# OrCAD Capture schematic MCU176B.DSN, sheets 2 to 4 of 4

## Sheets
2 2_Peripherals: size A3
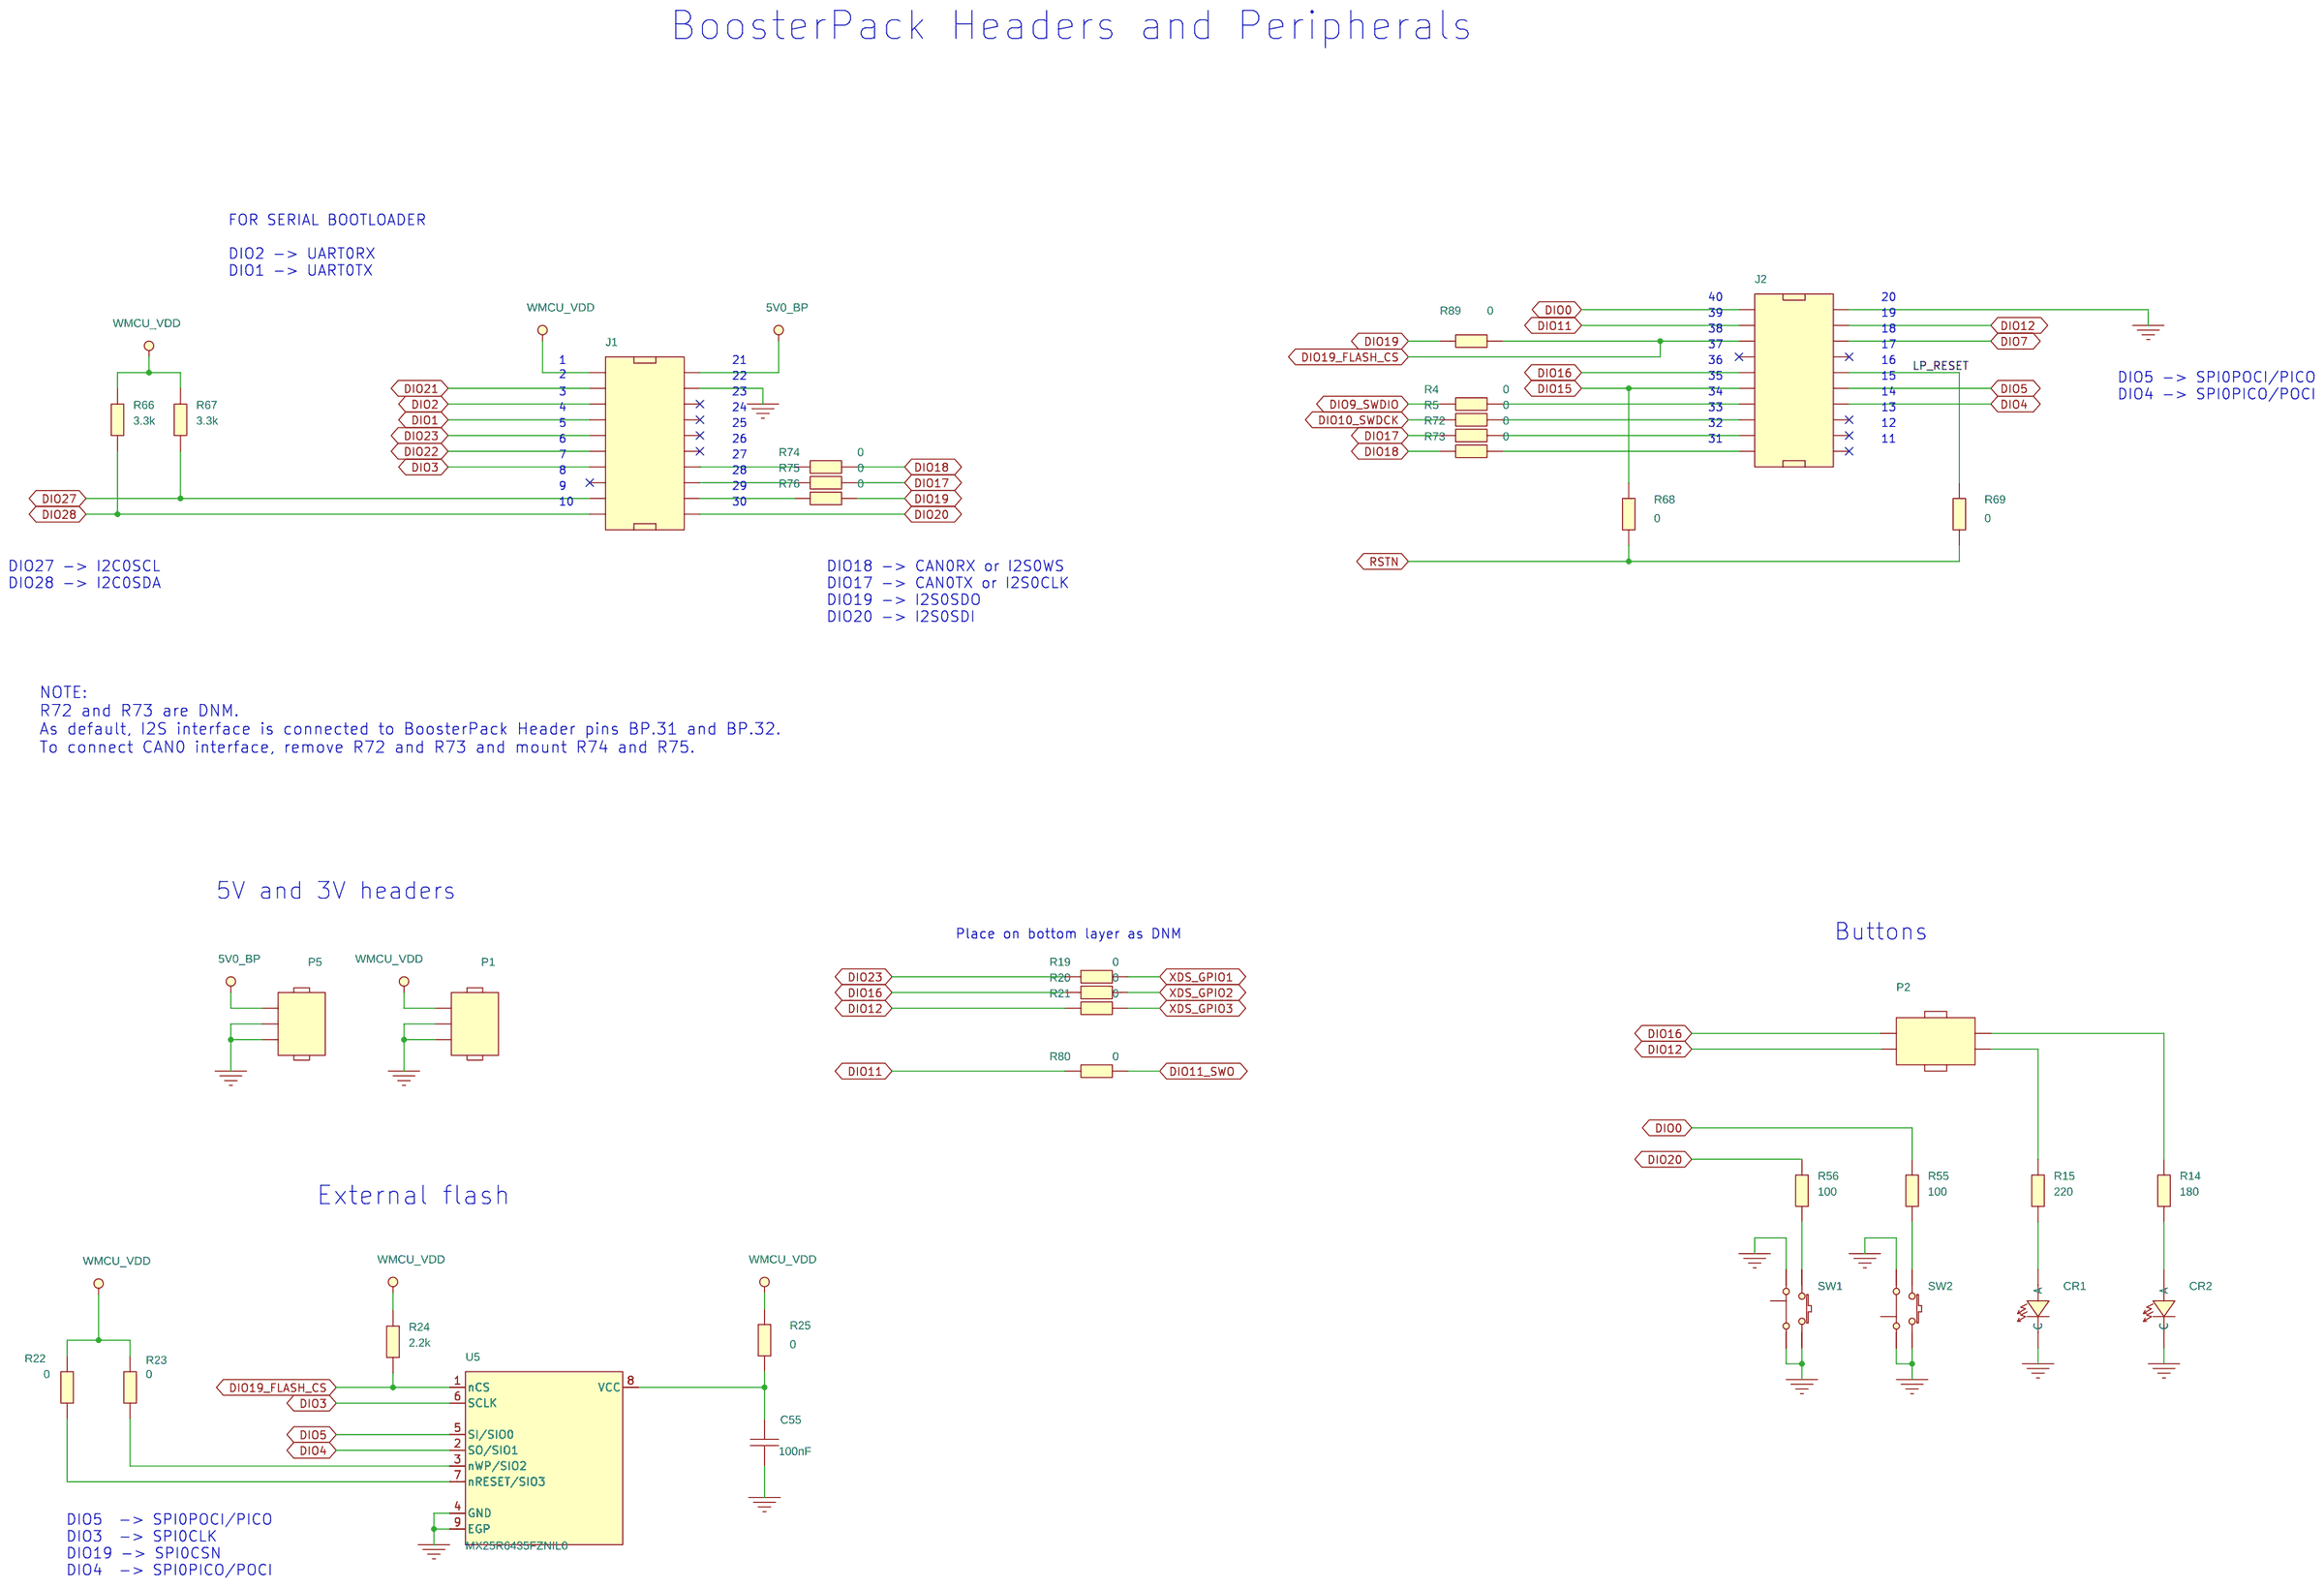
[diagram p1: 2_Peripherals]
3 3_Debugger Interface: size A3
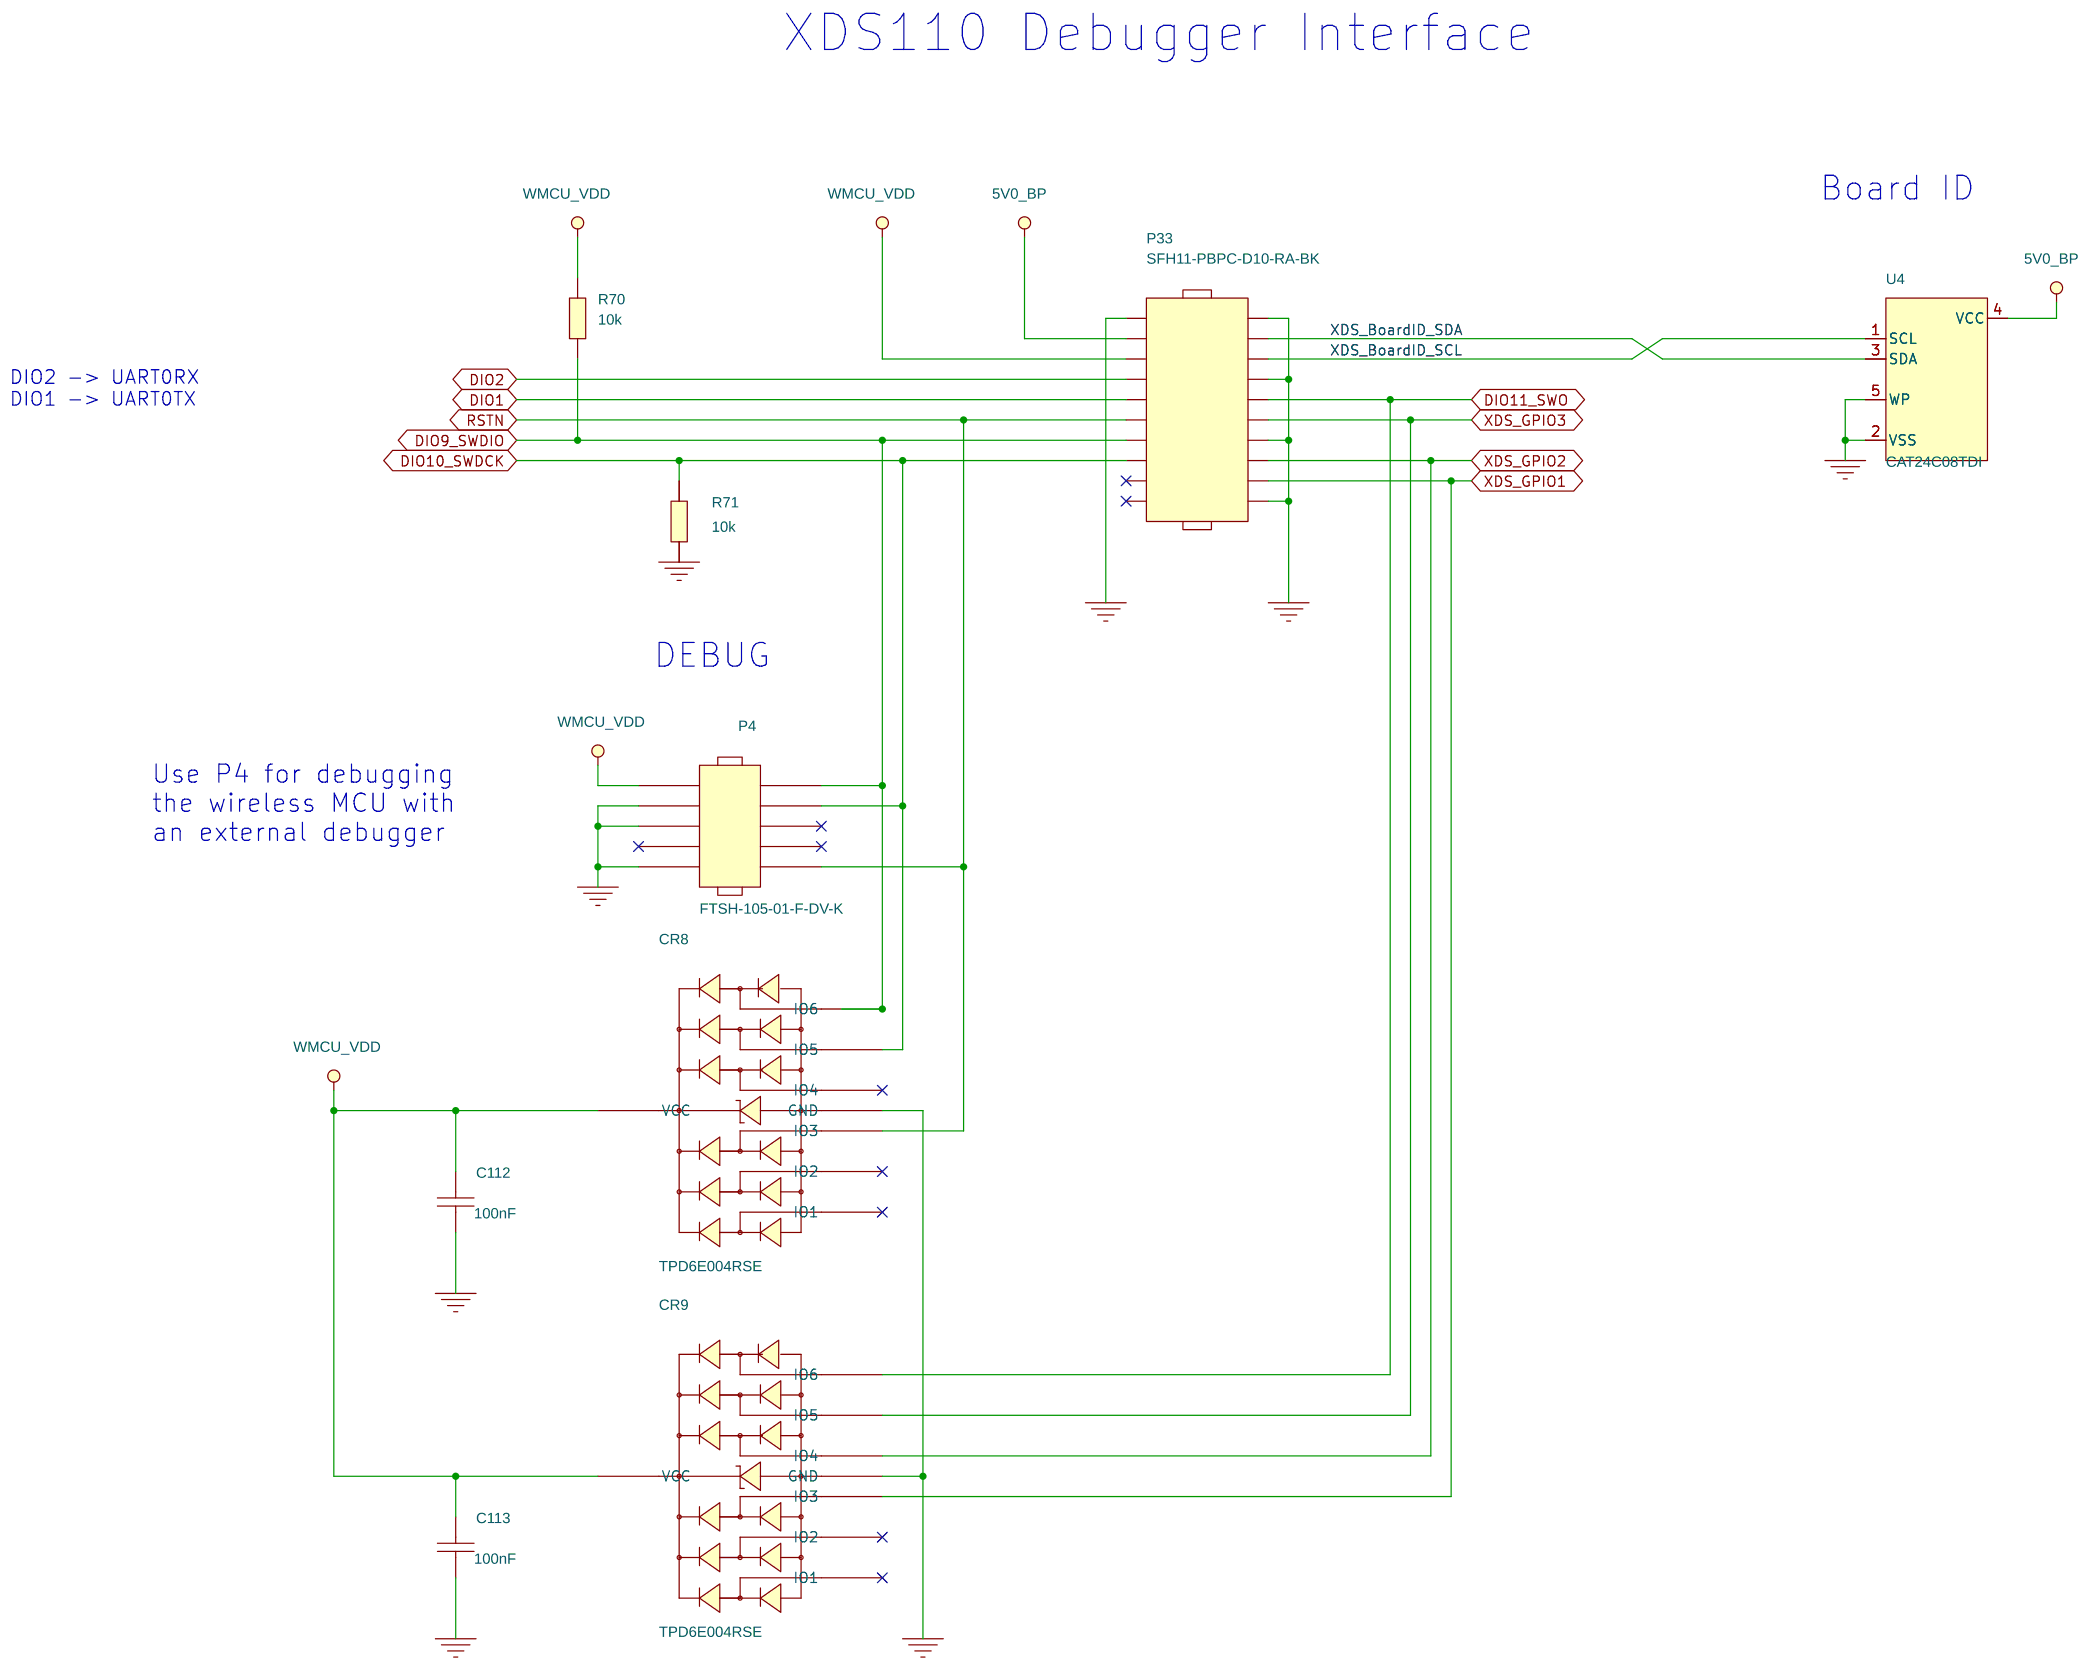
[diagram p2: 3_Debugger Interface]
4 4_Mech: size A3
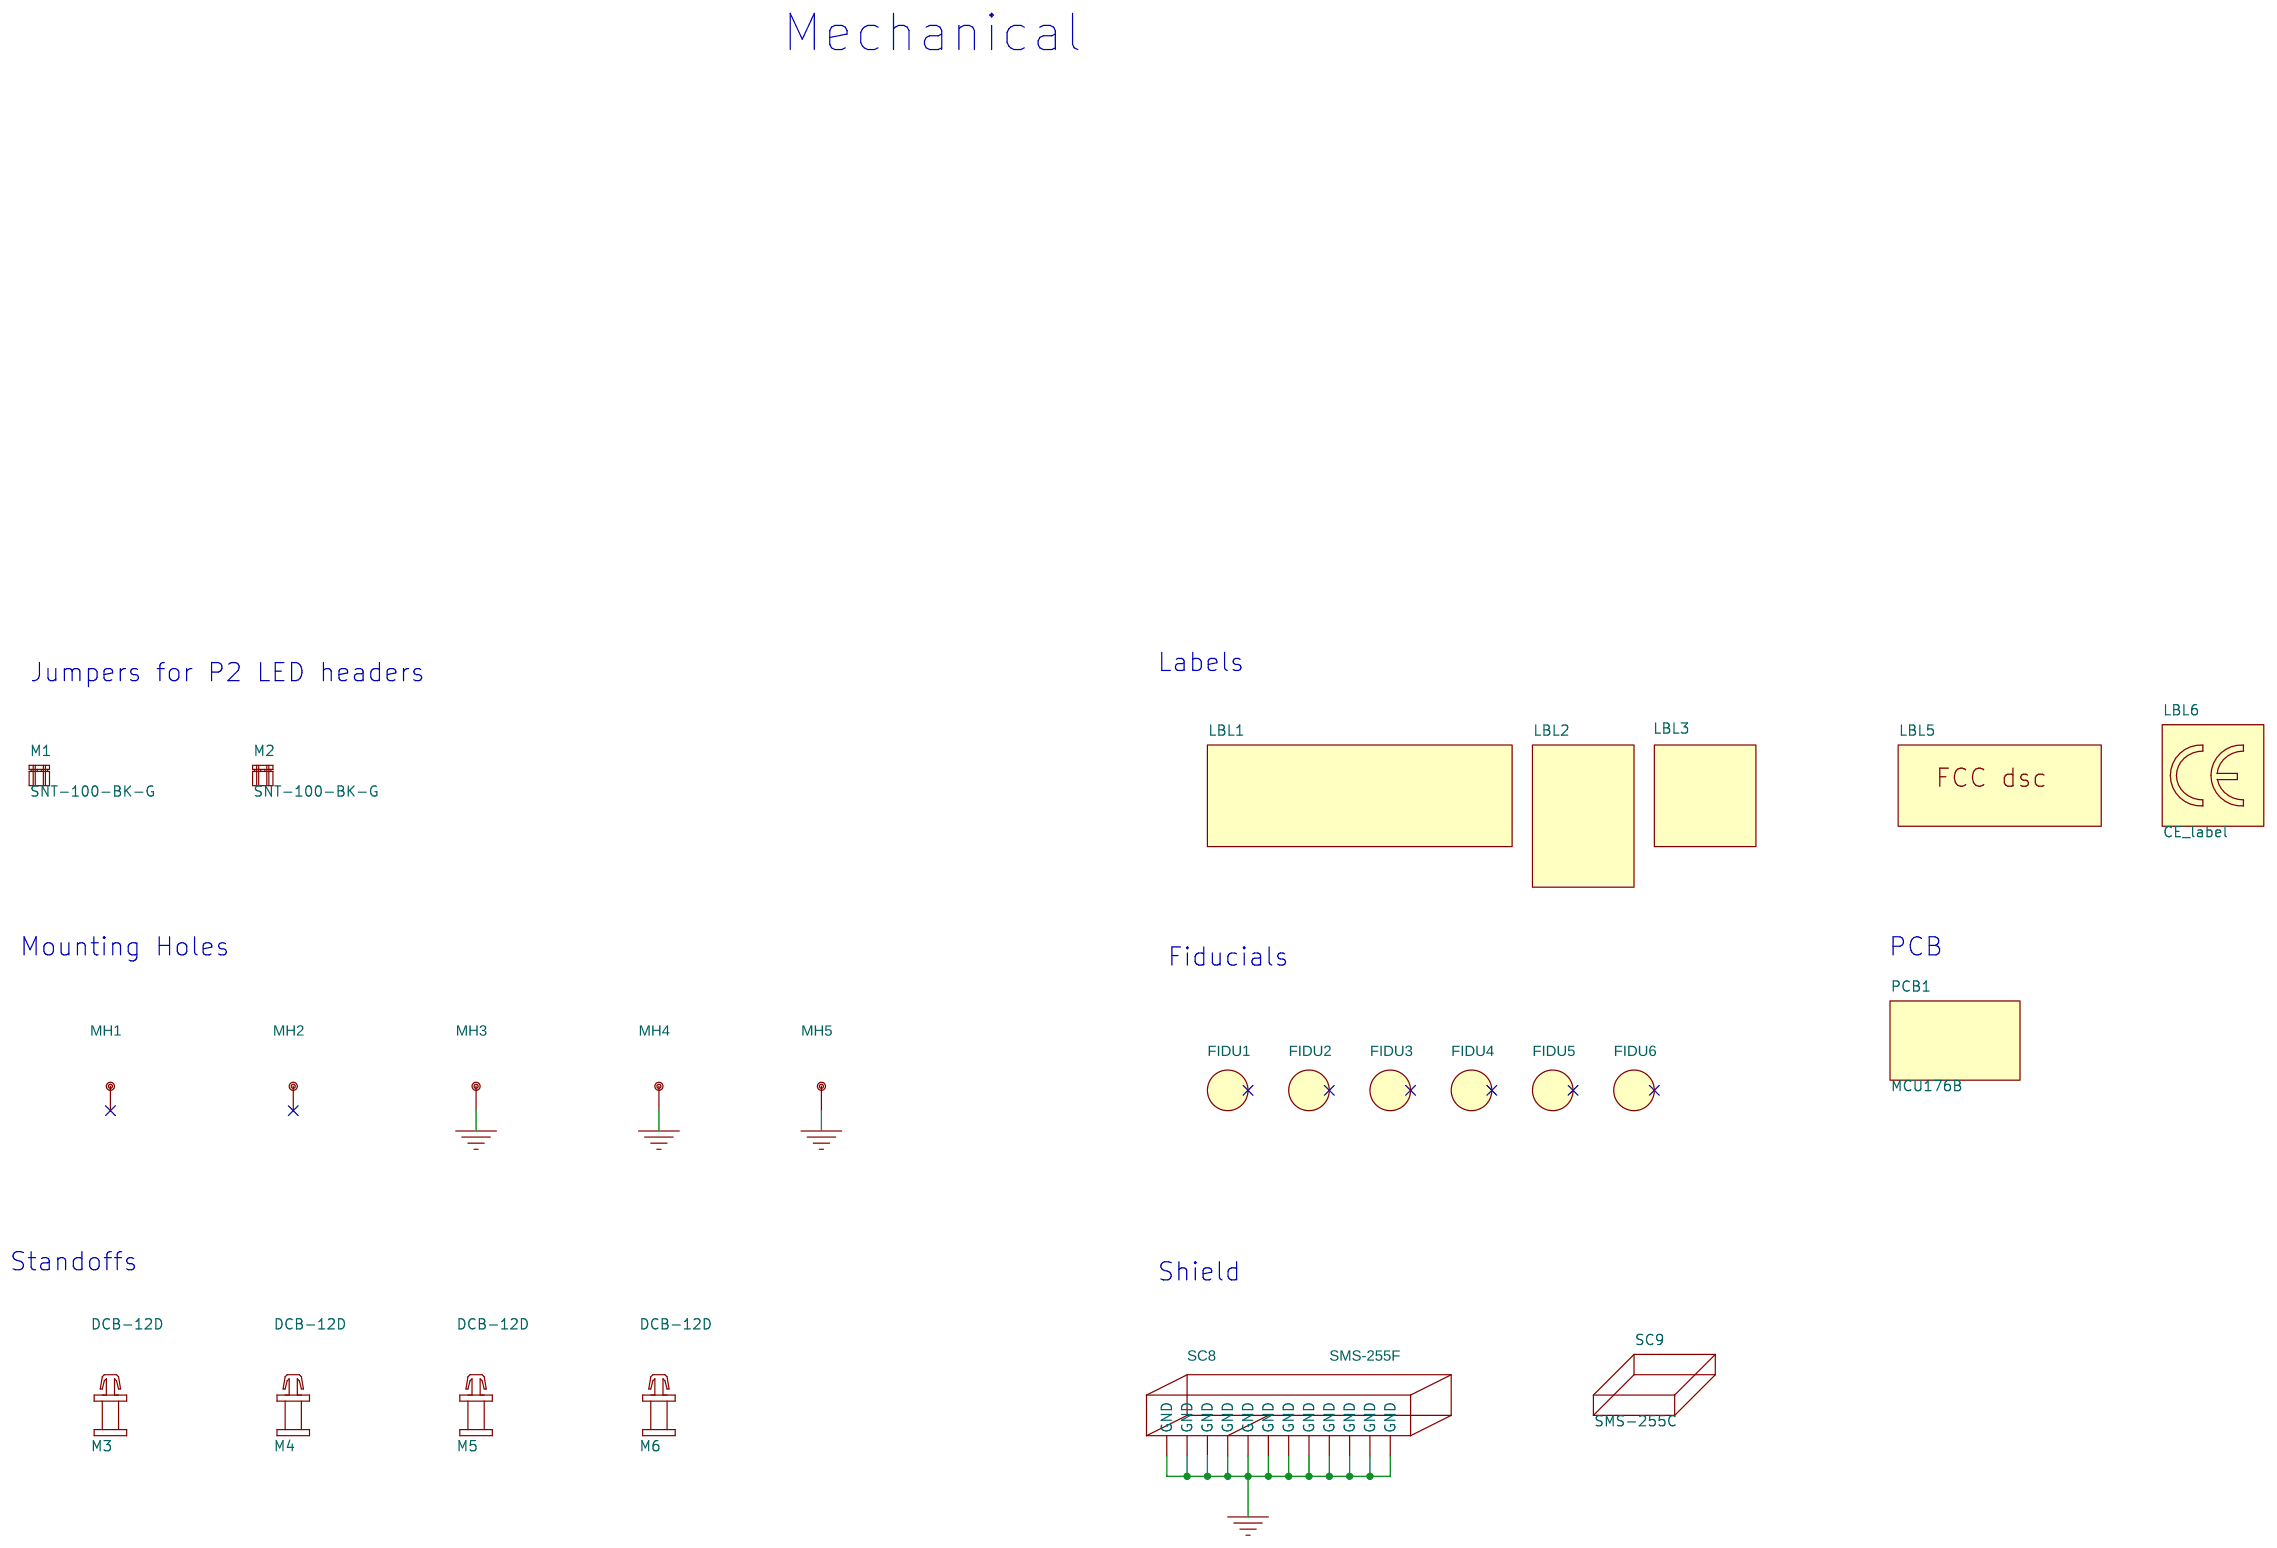
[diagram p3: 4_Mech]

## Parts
sheet 2_Peripherals
C55  100nF  [CAPC0603X35B2N]
CR1  150060VS55040  [LEDC1608X50F2N]
CR2  150060RS55040  [LEDC1608X50F2N]
J1  SSQ-110-23-L-D  [SAMTEC_SSQ11023LD_A2B]
J2  SSQ-110-23-L-D  [SAMTEC_SSQ11023LD_A2B]
P1  BB02-HC031-KB1-603000  [GRADCONN_BB02HC031KB1603000_A2B]
P2  BB02-HJ041-KB1-603000  [GRADCONN_BB02HJ041KB1603000_A2B]
P5  BB02-HC031-KB1-603000  [GRADCONN_BB02HC031KB1603000_A2B]
R4  0  [RESC1005X40A2N]
R5  0  [RESC1005X40A2N]
R14  180  [RESC1005X40A2N]
R15  220  [RESC1005X40A2N]
R19  0  [RESC1608X55A2N]
R20  0  [RESC1608X55A2N]
R21  0  [RESC1608X55A2N]
R22  0  [RESC0603X35B2N]
R23  0  [RESC0603X35B2N]
R24  2.2k  [RESC0603X35B2N]
R25  0  [RESC1608X55A2N]
R55  100  [RESC1005X40A2N]
R56  100  [RESC1005X40A2N]
R66  3.3k  [RESC0603X35B2N]
R67  3.3k  [RESC0603X35B2N]
R68  0  [RESC1005X40A2N]
R69  0  [RESC1005X40A2N]
R72  0  [RESC1005X40A2N]
R73  0  [RESC1005X40A2N]
R74  0  [RESC1005X40A2N]
R75  0  [RESC1005X40A2N]
R76  0  [RESC1005X40A2N]
R80  0  [RESC1608X55A2N]
R89  0  [RESC0603X35B2N]
SW1  1188E-1K2  [SW_1188E1K2V_A2N]
SW2  1188E-1K2  [SW_1188E1K2V_A2N]
U5  MX25R6435FZNIL0  [SON127P600X500X80-9A2N]
sheet 3_Debugger Interface
C112  100nF  [CAPC0603X35B2N]
C113  100nF  [CAPC0603X35B2N]
CR8  TPD6E004RSE  [QFNFC50P150X150X60-8A2N]
CR9  TPD6E004RSE  [QFNFC50P150X150X60-8A2N]
P4  FTSH-105-01-F-DV-K  [SAMTEC_FTSH-105-01-F-DV-K-10N]
P33  SFH11-PBPC-D10-RA-BK  [SULLINS_SFH11PBPCD10RABK_A2B]
R70  10k  [RESC1005X40B2N]
R71  10k  [RESC1005X40B2N]
U4  CAT24C08TDI  [SOT95P280X100-5A2N]
sheet 4_Mech
FIDU1  FIDU_1.27mm  [FID127X142]
FIDU2  FIDU_1.27mm  [FID127X142]
FIDU3  FIDU_1.27mm  [FID127X142]
FIDU4  FIDU_1.27mm  [FID127X142]
FIDU5  FIDU_1.27mm  [FID127X142]
FIDU6  FIDU_1.27mm  [FID127X142]
LBL1  TI_LOGO  [TI_LOGO_1]
LBL2  TRASH_7mm  [TRASH_7MM]
LBL3  ESD_LABEL_5X5mm  [ESD_LABEL_5X5]
LBL5  LABEL_FOR_EVALUATION_ONLY  [LABEL_FOR_EVALUATION_ONLY]
LBL6  CE_label  [CE_MARKING]
M1  SNT-100-BK-G  [SAMTEC_SNT100BKG]
M2  SNT-100-BK-G  [SAMTEC_SNT100BKG]
M3  DCB-12D  [MECH_DCB12D_A2B]
M4  DCB-12D  [MECH_DCB12D_A2B]
M5  DCB-12D  [MECH_DCB12D_A2B]
M6  DCB-12D  [MECH_DCB12D_A2B]
MH1  HOLE_3.2mm_PAD_3.8mm_PTH  [MTG320_380]
MH2  HOLE_3.2mm_PAD_3.8mm_PTH  [MTG320_380]
MH3  HOLE_3.2mm_PAD_3.8mm_PTH  [MTG320_380]
MH4  HOLE_3.2mm_PAD_3.8mm_PTH  [MTG320_380]
MH5  HOLE_1.1mm_PTH  [MTG110_170]
PCB1  MCU176B  [TI_MCUXX]
SC8  SMS-255F  [MECH_SMS255_A2N]
SC9  SMS-255C

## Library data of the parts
C55 C112 C113 = CAPACITOR: CAPACITOR, CERAMIC X7S, 100nF, -10%/+10%, 16V, -55DEGC/+125DEGC, 0201, SMD; ALT_SYMBOLS: CAPC0603X35B2L,CAPC0603X35B2M; Additional Datasheet URL: https://pim.murata.com/en-us/pim/details?partNum=GRM033C71C104KE14%23; Budgetary Price: .00785 EUR; Country of Origin: China, Japan, Philippines, Singapore, Thailand; Datasheet URL: https://pim.murata.com/asset/pim4/ceramicCapacitorSMD/GRM033C71C104KE14-01A-EN_PDF_CERAMICCAPACITORSMD?lastModifiedDatetime=20250813141327; Dielectric Type: X7S; Lead Time: 11; Mass: 0.00033g; Maximum Operating Temperature: +125DEGC; Maximum Tolerance: +10%; Minimum Operating Temperature: -55DEGC; Minimum Tolerance: -10%; Mounting Type: SMD; NOTEfied URL: https://webinterface.notefied-dynamic-precision.com/item/20463738; PCB Package: 0201; Packing Size: 15000; Packing Type: Tape & Reel; Part Number: 02-09228; Part Type: Capacitor|CERAMIC|0201|STANDARD; REACH/SVHC Compliance: Compliant; REACH/SVHC Details: SVHC List Version Jan 23, 2024 (240); REACH/SVHC Source: REACH Declaration & Material Declaration; REACH/SVHC Status: Unaffected; ROHS: Compliant; Rated Voltage: 16V; Status: Released; Texas Part Number: TEXAS_00001; Texas Part Status: Under Review; Type: Capacitor; Vendor: MURATA; Vendor Part Number: GRM033C71C104KE14D; Vendor Part Status: Active
CR1 = LED: OPTO, LED, AlInGaP, GREEN, STRAIGHT, 573nm, 2V, 0.02A, 0.048W, 0603, SMD; ALT_SYMBOLS: LEDC1608X50F2L,LEDC1608X50F2M; Additional Datasheet URL: https://www.we-online.com/en/components/products/WL-SMCD#150060VS55040; Country of Origin: Taiwan; Datasheet URL: https://www.we-online.com/components/products/datasheet/150060VS55040.pdf; Mass: N/A; Maximum Operating Temperature: +85DEGC; Minimum Operating Temperature: -40DEGC; Mounting Type: SMD; NOTEfied URL: https://dev-webinterface.dpserver.no/item/49590251; PCB Package: 0603; Packing Size: 4000; Packing Type: Tape & Reel; Part Number: 15-03575; Part Type: Opto|LED|0603; REACH/SVHC Details: SVHC List Version; ROHS: Compliant; Rated Current: 0.02A; Rated Power: 0.048W; Rated Voltage: 2V; Revision: R008; Status: Released; Type: Opto; Vendor: WURTH; Vendor Part Status: Active
CR2 = LED: OPTO, LED, AlInGaP, RED, STRAIGHT, 624nm, 2V, 0.02A, 0.048W, 0603, SMD; ALT_SYMBOLS: LEDC1608X50F2L,LEDC1608X50F2M; Additional Datasheet URL: https://www.we-online.com/en/components/products/WL-SMCD#150060RS55040; Country of Origin: Taiwan; Datasheet URL: https://www.we-online.com/components/products/datasheet/150060RS55040.pdf; Mass: N/A; Maximum Operating Temperature: +85DEGC; Minimum Operating Temperature: -40DEGC; Mounting Type: SMD; NOTEfied URL: https://dev-webinterface.dpserver.no/item/49590283; PCB Package: 0603; Packing Size: 4000; Packing Type: Tape & Reel; Part Number: 15-03577; Part Type: Opto|LED|0603; REACH/SVHC Details: SVHC List Version; ROHS: Compliant; Rated Current: 0.02A; Rated Power: 0.048W; Rated Voltage: 2V; Revision: R008; Status: Released; Type: Opto; Vendor: WURTH; Vendor Part Status: Active
J1 J2 = CONN_HEADER_2X10_J_S_V1: CONNECTOR, HEADER, FEMALE, STRAIGHT, 2 ROW(S), 20 PIN(S), 2.54mm, PTH; ALT_SYMBOLS: SAMTEC_SSQ11023LD_A2A,SAMTEC_SSQ11023LD_A2C; Additional Datasheet URL: https://www.samtec.com/products/ssq-110-23-l-d; AutoDoc File: http://notefied-dynamic-precision.com/DB/Apps/Desktop/Item/Object.aspx?id=104387; Budget Currency: USD; Budget Price: 2.14; Budgetary Price: 2.62146 USD; Country of Origin: China, Costa Rica, Malaysia, Singapore, Taiwan, United States, Vietnam; Datasheet URL: https://suddendocs.samtec.com/catalog_english/ssq_th.pdf; Datasheet URL 1: http://suddendocs.samtec.com/prints/ssq-1xx-xx-xxx-x-xx-xxx-xx-x-mkt.pdf; Datasheet URL 2: http://suddendocs.samtec.com/catalog_english/ssq_th.pdf; Definied Quality: INDUSTRIAL; Esd Level: N/A; FPLIST: SAMTEC_SSQ11023LD_A2B,SAMTEC_SSQ11023LD_A2C,SAMTEC_SSQ11023LD_A2A; Lead Time: 12; LifeCycle Status: ACTIVE; MPN Status: ACTIVE; MSL: N/A; Manufacturer: SAMTEC; Mass: 2.45594g; Max Oper Temp: +125DEGC; Maximum Operating Temperature: +125DEGC; Min Oper Temp: -55DEGC; Minimum Operating Temperature: -55DEGC; Mounting Type: PTH; NOTE Status: PREFERRED; NOTEfied URL: https://dev-webinterface.dpserver.no/item/7324084; No Of Pos: 20; No Of Rows: 2; Number of Positions: 20; Number of Rows: 2; Packing Size: 21; Packing Type: Bulk; Part Number: 06-04997; Part Type: Connector|HEADER|STANDARD; Pitch: 2.54mm; REACH/SVHC Compliance: Compliant; REACH/SVHC Details: SVHC List Version Jan 12, 2017 (173); REACH/SVHC Source: REACH Declaration & Material Declaration; REACH/SVHC Status: Unaffected; ROHS: Compliant; Rated Current: 6.3A; Rated Voltage: 465VAC / 655VDC; Revision: R029; RoHS Status: ROHS_COMPLIANT; Rtd Current: 6.3A; Status: Released; Texas Part Status: Under Review; Type: Connector; Vendor: SAMTEC; Vendor Part Status: Active; WEIGHT: 2.45594g
P1 P5 = CONN_HEADER_3_P_S: CONNECTOR, HEADER, MALE, STRAIGHT, 1 ROW(S), 3 PIN(S), PITCH 2.54mm, PTH; ALT_SYMBOLS: GRADCONN_BB02HC031KB1603000_A2A,GRADCONN_BB02HC031KB1603000_A2C; Additional Datasheet URL: https://www.gradconn.com/Products/BoardToBoard/All/BB02-HC; AutoDoc File: http://notefied-dynamic-precision.com/DB/Apps/Desktop/Item/Object.aspx?id=104636; Country of Origin: Missing Info; Datasheet URL: https://www.gradconn.com/files/Drawings/BB02-HC.pdf; Datasheet URL 1: http://www.gradconn.com/Files/Drawings/BB02-HC.pdf; Datasheet URL 2: http://www.gradconn.com/Files/Specs/BTB-2.54mm-Header-specification.pdf; MPN Status: ACTIVE; Manufacturer: GRADCONN; Mass: N/A; Max Oper Temp: +105DEGC; Maximum Operating Temperature: +105DEGC; Min Oper Temp: -40DEGC; Minimum Operating Temperature: -40DEGC; Mounting Type: PTH; NOTE Status: PREFERRED; NOTEfied URL: https://dev-webinterface.dpserver.no/item/7324030; No Of Pos: 3; No Of Rows: 1; Number of Positions: 3; Number of Rows: 1; Packing Size: N/A; Packing Type: Missing Info; Part Number: 06-05038; Part Type: Connector|HEADER|STANDARD; Pitch: 2.54mm; REACH/SVHC Compliance: Compliant; REACH/SVHC Details: SVHC List Version Jun 20, 2016; REACH/SVHC Source: RoHS & REACH Declaration; REACH/SVHC Status: Unaffected; ROHS: Compliant; Rated Current: 3A; Rated Voltage: 250V; Revision: R023; RoHS Status: ROHS_COMPLIANT; Rtd Current: 3A; Rtd Voltage: 250V; Status: Released; Texas Part Status: Under Review; Type: Connector; Vendor: GRADCONN; Vendor Part Status: Active
P2 = CONN_HEADER_2X2_P: CONNECTOR, HEADER, MALE, STRAIGHT, 2 ROW(S), 4 PIN(S), PITCH 2.54mm, PTH; ALT_SYMBOLS: GRADCONN_BB02HJ041KB1603000_A2A,GRADCONN_BB02HJ041KB1603000_A2C; Additional Datasheet URL: https://www.gradconn.com/Products/BoardToBoard/All/BB02-HJ; AutoDoc File: http://notefied-dynamic-precision.com/DB/Apps/Desktop/Item/Object.aspx?id=104391; Country of Origin: Missing Info; Datasheet URL: https://www.gradconn.com/files/Drawings/BB02-HJ.pdf; Datasheet URL 1: http://www.gradconn.com/Files/Drawings/BB02-HJ.pdf; Datasheet URL 2: http://www.gradconn.com/Files/Specs/BTB-2.54mm-Header-specification.pdf; MPN Status: ACTIVE; Manufacturer: GRADCONN; Mass: N/A; Max Oper Temp: +105DEGC; Maximum Operating Temperature: +105DEGC; Min Oper Temp: -40DEGC; Minimum Operating Temperature: -40DEGC; Mounting Type: PTH; NOTE Status: PREFERRED; NOTEfied URL: https://dev-webinterface.dpserver.no/item/7324086; No Of Pos: 4; No Of Rows: 2; Number of Positions: 4; Number of Rows: 2; Packing Size: N/A; Packing Type: Missing Info; Part Number: 06-04999; Part Type: Connector|HEADER|STANDARD; Pitch: 2.54mm; REACH/SVHC Compliance: Compliant; REACH/SVHC Details: SVHC List Version Jun 20, 2016 (169); REACH/SVHC Source: RoHS & REACH Declaration; REACH/SVHC Status: Unaffected; ROHS: Compliant; Rated Current: 3A; Revision: R032; RoHS Status: ROHS_COMPLIANT; Rtd Current: 3A; Status: Released; Texas Part Status: Under Review; Type: Connector; Vendor: GRADCONN; Vendor Part Status: Active
R4 R5 R68 R69 R72-R76 = RESISTOR: RESISTOR, THICK FILM, JUMPER, 0, 0R/+0.05R, 1A, -55DEGC/+155DEGC, 0402, SMD; ALT_SYMBOLS: RESC1005X40A2L,RESC1005X40A2M; Additional Datasheet URL: https://www.koaspeer.com/products/resistors/general-purpose/rk73z/; Budgetary Price: .00494 USD; Country of Origin: China, Japan; Datasheet URL: https://www.koaspeer.com/pdfs/RK73Z.pdf; Lead Time: 7; Mass: 0.00068g; Maximum Operating Temperature: +155DEGC; Maximum Temperature Coefficient: N/A; Maximum Tolerance: +0.05R; Minimum Operating Temperature: -55DEGC; Minimum Temperature Coefficient: N/A; Minimum Tolerance: 0R; Mounting Type: SMD; NOTEfied URL: https://webinterface.notefied-dynamic-precision.com/item/7187921; PCB Package: 0402; Packing Size: 10000; Packing Type: Tape & Reel; Part Number: 01-01784; Part Type: Resistor|0402|JUMPER; REACH/SVHC Compliance: Compliant; REACH/SVHC Details: SVHC List Version Jun 14, 2023 (235); REACH/SVHC Source: Material Declaration; REACH/SVHC Status: Unaffected; ROHS: Exempt; Rated Current: 1A; Rated Power: N/A; Rated Voltage: N/A; Resistor Type: THICK FILM; Status: Released; Type: Resistor; Vendor: KOA SPEER; Vendor Part Number: RK73Z1ETTP; Vendor Part Status: Active
R14 = RESISTOR: RESISTOR, THICK FILM, 180, -5%/+5%, 0.063W, 50V, -55DEGC/+155DEGC, 0402, SMD; ALT_SYMBOLS: RESC1005X40A2L,RESC1005X40A2M; Additional Datasheet URL: https://www.vishay.com/en/product/20035/; Budgetary Price: .004 EUR; Country of Origin: Missing Info; Datasheet URL: https://www.vishay.com/docs/20035/dcrcwe3.pdf; Lead Time: 31; Mass: 0.00065g; Maximum Operating Temperature: +155DEGC; Maximum Temperature Coefficient: +200PPM/DEGC; Maximum Tolerance: +5%; Minimum Operating Temperature: -55DEGC; Minimum Temperature Coefficient: -200PPM/DEGC; Minimum Tolerance: -5%; Mounting Type: SMD; NOTEfied URL: https://dev-webinterface.dpserver.no/item/7186410; PCB Package: 0402; Packing Size: 10000; Packing Type: Tape & Reel; Part Number: 01-01205; Part Type: Resistor|0402|STANDARD; REACH/SVHC Compliance: Compliant; REACH/SVHC Details: SVHC List Version Jan 23, 2024 (240); REACH/SVHC Source: REACH Declaration & Material Declaration; REACH/SVHC Status: Unaffected; ROHS: Exempt; Rated Current: N/A; Rated Power: 0.063W; Rated Voltage: 50V; Resistor Type: THICK FILM; Status: Released; Type: Resistor; Vendor: VISHAY; Vendor Part Number: CRCW0402180RJNED; Vendor Part Status: Active
R15 = RESISTOR: RESISTOR, THICK FILM, 220, -5%/+5%, 0.063W, 50V, -55DEGC/+155DEGC, 0402, SMD; ALT_SYMBOLS: RESC1005X40A2L,RESC1005X40A2M; Additional Datasheet URL: https://www.vishay.com/en/product/20035/; Budgetary Price: .004 EUR; Country of Origin: Israel; Datasheet URL: https://www.vishay.com/docs/20035/dcrcwe3.pdf; Lead Time: 31; Mass: 0.00065g; Maximum Operating Temperature: +155DEGC; Maximum Temperature Coefficient: +200PPM/DEGC; Maximum Tolerance: +5%; Minimum Operating Temperature: -55DEGC; Minimum Temperature Coefficient: -200PPM/DEGC; Minimum Tolerance: -5%; Mounting Type: SMD; NOTEfied URL: https://dev-webinterface.dpserver.no/item/7186405; PCB Package: 0402; Packing Size: 10000; Packing Type: Tape & Reel; Part Number: 01-01207; Part Type: Resistor|0402|STANDARD; REACH/SVHC Compliance: Compliant; REACH/SVHC Details: SVHC List Version Jan 23, 2024 (240); REACH/SVHC Source: REACH Declaration & Material Declaration; REACH/SVHC Status: Unaffected; ROHS: Exempt; Rated Current: N/A; Rated Power: 0.063W; Rated Voltage: 50V; Resistor Type: THICK FILM; Status: Released; Type: Resistor; Vendor: VISHAY; Vendor Part Number: CRCW0402220RJNED; Vendor Part Status: Active
R19-R21 R25 R80 = RESISTOR: RESISTOR, THICK FILM, JUMPER, 0, 0R/0.05R, 0.1W, 1A, -55DEGC/+155DEGC, 0603, SMD; ALT_SYMBOLS: RESC1608X55A2L,RESC1608X55A2M; Additional Datasheet URL: https://www.yageogroup.com/products/Resistors/part/RC0603JR-070RL; Budgetary Price: .00384 USD; Country of Origin: Taiwan, China; Datasheet URL: https://www.yageogroup.com/content/datasheet/asset/file/PYU-RC_GROUP_51_ROHS_L; Lead Time: 18; Mass: 0.0024733g; Maximum Operating Temperature: +155DEGC; Maximum Temperature Coefficient: N/A; Maximum Tolerance: +0.05R; Minimum Operating Temperature: -55DEGC; Minimum Temperature Coefficient: N/A; Minimum Tolerance: 0R; Mounting Type: SMD; NOTEfied URL: https://webinterface.notefied-dynamic-precision.com/item/7192714; PCB Package: 0603; Packing Size: 5000; Packing Type: Tape & Reel; Part Number: 01-03278; Part Type: Resistor|0603|JUMPER; REACH/SVHC Compliance: Compliant; REACH/SVHC Details: SVHC List Version Jan 19, 2021 (211); REACH/SVHC Source: REACH Declaration & Material Declaration; REACH/SVHC Status: Unaffected; ROHS: Exempt; Rated Current: 1A; Rated Power: 0.1W; Resistor Type: THICK FILM; Status: Released; Type: Resistor; Vendor: YAGEO; Vendor Part Number: RC0603JR-070RL; Vendor Part Status: Active
R22 R23 R89 = RESISTOR: RESISTOR, THICK FILM, JUMPER, 0, 0R/+0.05R, 0.05W, 1A, -55DEGC/+155DEGC, 0201, SMD; ALT_SYMBOLS: RESC0603X35B2L,RESC0603X35B2M; Additional Datasheet URL: https://www.vishay.com/en/product/20052/; Budgetary Price: .00605 EUR; Country of Origin: China, Israel, Malaysia; Datasheet URL: https://www.vishay.com/docs/20052/crcw0201e3.pdf; Lead Time: 20; Mass: 0.000143039g; Maximum Operating Temperature: +155DEGC; Maximum Temperature Coefficient: N/A; Maximum Tolerance: +0.05R; Minimum Operating Temperature: -55DEGC; Minimum Temperature Coefficient: N/A; Minimum Tolerance: 0R; Mounting Type: SMD; NOTEfied URL: https://webinterface.notefied-dynamic-precision.com/item/7195182; PCB Package: 0201; Packing Size: 10000; Packing Type: Tape & Reel; Part Number: 01-04043; Part Type: Resistor|0201|JUMPER; REACH/SVHC Compliance: Compliant; REACH/SVHC Details: SVHC List Version Jan 23, 2024 (240); REACH/SVHC Source: REACH Declaration & Material Declaration; REACH/SVHC Status: Unaffected; ROHS: Exempt; Rated Current: 1A; Rated Power: 0.05W; Rated Voltage: N/A; Resistor Type: THICK FILM; Status: Released; Texas Part Number: TEXAS_00014; Texas Part Status: Under Review; Type: Resistor; Vendor: VISHAY; Vendor Part Number: CRCW02010000Z0ED; Vendor Part Status: Active
R24 = RESISTOR: RESISTOR, THICK FILM, 2.2k, -5%/+5%, 0.05W, 30V, -55DEGC/+155DEGC, 0201, SMD; ALT_SYMBOLS: RESC0603X35B2L,RESC0603X35B2M; Additional Datasheet URL: https://www.vishay.com/en/product/20052/; Budgetary Price: .0077 EUR; Country of Origin: China, Malaysia; Datasheet URL: https://www.vishay.com/docs/20052/crcw0201e3.pdf; Lead Time: 20; Mass: 0.00017g; Maximum Operating Temperature: +155DEGC; Maximum Temperature Coefficient: +200PPM/DEGC; Maximum Tolerance: +5%; Minimum Operating Temperature: -55DEGC; Minimum Temperature Coefficient: -200PPM/DEGC; Minimum Tolerance: -5%; Mounting Type: SMD; NOTEfied URL: https://webinterface.notefied-dynamic-precision.com/item/7195548; PCB Package: 0201; Packing Size: 10000; Packing Type: Tape & Reel; Part Number: 01-04180; Part Type: Resistor|0201|STANDARD; REACH/SVHC Compliance: Compliant; REACH/SVHC Details: SVHC List Version Jan 23, 2024 (240); REACH/SVHC Source: REACH Declaration & Material Declaration; REACH/SVHC Status: Unaffected; ROHS: Exempt; Rated Current: N/A; Rated Power: 0.05W; Rated Voltage: 30V; Resistor Type: THICK FILM; Status: Released; Type: Resistor; Vendor: VISHAY; Vendor Part Number: CRCW02012K20JNED; Vendor Part Status: Active
R55 R56 = RESISTOR: RESISTOR, THICK FILM, 100, -5%/+5%, 0.063W, 50V, -55DEGC/+155DEGC, 0402, SMD; ALT_SYMBOLS: RESC1005X40A2L,RESC1005X40A2M; Additional Datasheet URL: https://www.vishay.com/en/product/20035/; Budgetary Price: .004 EUR; Country of Origin: United States; Datasheet URL: https://www.vishay.com/docs/20035/dcrcwe3.pdf; Lead Time: 31; Mass: 0.00065g; Maximum Operating Temperature: +155DEGC; Maximum Temperature Coefficient: +200PPM/DEGC; Maximum Tolerance: +5%; Minimum Operating Temperature: -55DEGC; Minimum Temperature Coefficient: -200PPM/DEGC; Minimum Tolerance: -5%; Mounting Type: SMD; NOTEfied URL: https://dev-webinterface.dpserver.no/item/7186034; PCB Package: 0402; Packing Size: 10000; Packing Type: Tape & Reel; Part Number: 01-01199; Part Type: Resistor|0402|STANDARD; REACH/SVHC Compliance: Compliant; REACH/SVHC Details: SVHC List Version Jan 23, 2024 (240); REACH/SVHC Source: REACH Declaration & Material Declaration; REACH/SVHC Status: Unaffected; ROHS: Exempt; Rated Current: N/A; Rated Power: 0.063W; Rated Voltage: 50V; Resistor Type: THICK FILM; Status: Released; Type: Resistor; Vendor: VISHAY; Vendor Part Number: CRCW0402100RJNED; Vendor Part Status: Active
R66 R67 = RESISTOR: RESISTOR, THICK FILM, 3.3k, -5%/+5%, 0.05W, 30V, -55DEGC/+155DEGC, 0201, SMD; ALT_SYMBOLS: RESC0603X35B2L,RESC0603X35B2M; Additional Datasheet URL: https://www.vishay.com/en/product/20052/; Budgetary Price: .009 EUR; Country of Origin: Taiwan; Datasheet URL: https://www.vishay.com/docs/20052/crcw0201e3.pdf; Lead Time: 20; Mass: 0.00017g; Maximum Operating Temperature: +155DEGC; Maximum Temperature Coefficient: +200PPM/DEGC; Maximum Tolerance: +5%; Minimum Operating Temperature: -55DEGC; Minimum Temperature Coefficient: -200PPM/DEGC; Minimum Tolerance: -5%; Mounting Type: SMD; NOTEfied URL: https://webinterface.notefied-dynamic-precision.com/item/7195545; PCB Package: 0201; Packing Size: 10000; Packing Type: Tape & Reel; Part Number: 01-04184; Part Type: Resistor|0201|STANDARD; ROHS: Exempt; Rated Current: N/A; Rated Power: 0.05W; Rated Voltage: 30V; Resistor Type: THICK FILM; Status: Released; Type: Resistor; Vendor: VISHAY; Vendor Part Number: CRCW02013K30JNED; Vendor Part Status: Active
SW1 SW2 = SWITCH_TACT_V2: SWITCH, TACTILE, 0.05A@12VDC, 0.05A@250VAC, SMD; ALT_SYMBOLS: SW_1188E1K2V_A2L,SW_1188E1K2V_A2M; Additional Datasheet URL: http://www.dip.com.tw/en/en-product-information/en-switch004/item/2445-1188; AutoDoc File: http://notefied-dynamic-precision.com/DB/Apps/Desktop/Item/Object.aspx?id=104642; Budgetary Price: .474 EUR; CLASS: IC; Country of Origin: China; Datasheet URL: http://www.dip.com.tw/en/en-product-information/en-switch004/item/download/2483_bfc264bcfe9982a2b01570916dd931c3; Datasheet URL 1: N/A; Datasheet URL 2: http://www.dip.com.tw/en/en-product-information/en-switch004; FPLIST: SW_1188E1K2V_A2N,SW_1188E1K2V_A2L,SW_1188E1K2V_A2M; Lead Time: 18; MPN: 1188E-1K2-V-TR; MPN Status: ACTIVE; Manufacturer: DIPTRONICS; Mass: N/A; Max Oper Temp: +70DEGC; Maximum Operating Temperature: +70DEGC; Min Oper Temp: -25DEGC; Minimum Operating Temperature: -25DEGC; Mounting Type: SMD; NOTE Status: PREFERRED; NOTEfied URL: https://dev-webinterface.dpserver.no/item/7329711; Packing Size: 1500; Packing Type: Tape & Reel; Part Number: 08-00293; Part Type: Switch|TACTILE; REACH/SVHC Compliance: Compliant; REACH/SVHC Details: SVHC List Version Dec 17, 2015 (168); REACH/SVHC Source: REACH Declaration; REACH/SVHC Status: Unaffected; ROHS: Compliant; Revision: R031; RoHS Status: ROHS_COMPLIANT; Rtd Current: 0.05A; Rtd Voltage: 12V; Status: Released; Texas Part Status: Under Review; Type: Switch; Vendor: DIPTRONICS; Vendor Part Number: 1188E-1K2-V-TR; Vendor Part Status: Active
U5 = IC_FLASH_MX25R6435F_WSON8: IC, MEMORY, FLASH, NOR, 64Mbit, 64M X 1bit / 32M X 2bit / 16M X 4bit, 80MHz, 1.65V TO 3.6V, WSON8-EP, SMD; ALT_SYMBOLS: SON127P600X500X80-9A2L,SON127P600X500X80-9A2M; Additional Datasheet URL: https://www.mxic.com.tw/en-us/products/NOR-Flash/Serial-NOR-Flash/Pages/spec.aspx?p=MX25R6435F&m=Serial%20NOR%20Flash&n=PM2138&epn=MX25R6435FZNIL0; Budgetary Price: 2.29345 USD; Country of Origin: Taiwan; Datasheet URL: https://www.mxic.com.tw/Lists/Datasheet/Attachments/8868/MX25R6435F,%20Wide%20Range,%2064Mb,%20v1.6.pdf; Frequency: 80MHz; Mass: N/A; Maximum Operating Temperature: +85DEGC; Minimum Operating Temperature: -40DEGC; Mounting Type: SMD; NOTEfied URL: https://webinterface.notefied-dynamic-precision.com/item/72608247; PCB Package: WSON8-EP; Packing Size: 570; Packing Type: Tray; Part Number: 18-40374; Part Type: IC|MEMORY|FLASH|NOR; REACH/SVHC Compliance: Compliant; REACH/SVHC Details: SVHC List Version Nov 05, 2025 (251); REACH/SVHC Source: RoHS & REACH Declaration; REACH/SVHC Status: Unaffected; ROHS: Compliant; Status: Released; Texas Part Status: Under Review; Type: IC; Vendor: MACRONIX; Vendor Part Status: Active
CR8 CR9 = DIODE_TVS_TPD6E004_QFN8_V1: DIODE, PROTECTION, ESD ARRAY - 6 CHANNELS, VCC:0.9V TO 5.5V, VBR:7V, -40DEGC/+85DEGC, QFN8, SMD; ALT_SYMBOLS: QFNFC50P150X150X60-8A2L,QFNFC50P150X150X60-8A2M; Additional Datasheet URL: https://www.ti.com/product/TPD6E004; AutoDoc File: https://notefied-dynamic-precision.com/DB/Apps/Desktop/Item/Object.aspx?id=74721; BU Name: DYNAMIC PRECISION GDANSK; Budget Currency: USD; Budget Price: 0.27; Budgetary Price: .16 USD; CLASS: IC; Client Status: UNDER_REVIEW; Country of Origin: China; Datasheet URL: https://www.ti.com/lit/gpn/TPD6E004; Datasheet URL 1: http://www.ti.com/lit/ds/symlink/tpd6e004.pdf; Datasheet URL 2: http://www.ti.com/litv/pdf/mpqf207b; FPLIST: QFN50P150X150X60-8N,QFN50P150X150X60-8AN; Lead Time: 12; Mass: 0.002839255g; Max Oper Temp: +85DEGC; Maximum Operating Temperature: +85DEGC; Min Oper Temp: -40DEGC; Minimum Operating Temperature: -40DEGC; Mounting Type: SMD; NOTEfied URL: https://webinterface.notefied-dynamic-precision.com/item/7366948; PCB Package: QFN8; Packing Size: 3000; Packing Type: Tape & Reel; Part Number: 14-05493; Part Type: Diode|PROTECTION; REACH/SVHC Compliance: Compliant; REACH/SVHC Details: SVHC List Version Jun 20, 2016 (169); REACH/SVHC Source: Material Declaration; REACH/SVHC Status: Unaffected; ROHS: Compliant; Rated Power: N/A; Rated Voltage: 7V; Revision: R039; RoHS Status: ROHS_COMPLIANT; Rtd Power: N/A; Rtd Voltage: 7V; Status: Released; Texas Part Status: Under Review; Type: Diode; Vendor: TEXAS INSTRUMENTS; Vendor Part Number: TPD6E004RSER; Vendor Part Status: Active; Weight: 0.0033g
P4 = CONN_HEADER_2X5: CONNECTOR, HEADER, MALE, STRAIGHT, 2 ROW(S), 10 PIN(S), PITCH 1.27mm, SMD; ALT_SYMBOLS: SAMTEC_FTSH10501FDVK_A2L,SAMTEC_FTSH10501FDVK_A2M,SAMTEC_FTSH10501FDVK_B2L,SAMTEC_FTSH10501FDVK_B2M; Additional Datasheet URL: https://www.samtec.com/products/ftsh-105-01-f-dv-k; AutoDoc File: http://notefied-dynamic-precision.com/DB/Apps/Desktop/Item/Object.aspx?id=50836; Budget Currency: USD; Budget Price: 1.700; Budgetary Price: 2.07959 USD; CLASS: IO; Country of Origin: China, Costa Rica, Malaysia, Singapore, Taiwan, United States, Vietnam; Datasheet URL: https://suddendocs.samtec.com/catalog_english/ftsh_smt.pdf; Datasheet URL 1: http://www.samtec.com/documents/webfiles/cpdf/FTSH-1XX-XX-XXX-DV-XXX-MKT.pdf; Datasheet URL 2: http://www.samtec.com/documents/webfiles/pdf/FTSH_SMT.PDF; FPLIST: SAMTEC_FTSH10501FDVK_A2N,SAMTEC_FTSH-105-01-F-DV-K-10N; Lead Time: 14; LifeCycle Status: MATURITY; MPN Status: ACTIVE; Manufacturer: SAMTEC; Mass: 0.31700g; Max Oper Temp: +125DEGC; Maximum Operating Temperature: +125DEGC; Min Oper Temp: -55DEGC; Minimum Operating Temperature: -55DEGC; Mounting Type: SMD; NOTE Status: PREFERRED; NOTEfied URL: https://webinterface.notefied-dynamic-precision.com/item/7308603; No Of Pos: 10; No Of Rows: 2; Number of Positions: 10; Number of Rows: 2; Old Footprint: SAMTEC_FTSH-105-01-F-DV-K-10N,CONN_MALE_2X5; Packing Size: 92; Packing Type: Tube; Part Number: 06-00166; Part Type: Connector|HEADER|STANDARD; Pitch: 1.27mm; REACH/SVHC Compliance: Compliant; REACH/SVHC Details: SVHC List Version Jun 10, 2022 (224); REACH/SVHC Source: REACH Declaration & Material Declaration; REACH/SVHC Status: Unaffected; ROHS: Compliant; Rated Current: 3.4A; Revision: R044; RoHS Status: ROHS_COMPLIANT; Rtd Current: 1.75A; Status: Released; Texas Part Status: Under Review; Type: Connector; Vendor: SAMTEC; Vendor Part Status: Active; WEIGHT: 0.65614g
P33 = CONN_HEADER_2X10_P_V3: CONNECTOR, HEADER, FEMALE, RIGHT ANGLE, 2 ROW(S), 20 PIN(S), PITCH 2.54mm, PTH; ALT_SYMBOLS: SULLINS_SFH11PBPCD10RABK_A2A,SULLINS_SFH11PBPCD10RABK_A2C; Additional Datasheet URL: https://www.sullinscorp.com/product/?pn=SFH11-PBPC-D10-RA-BK&toggle=in; Budgetary Price: .78488 USD; Country of Origin: United States; Datasheet URL: https://s3.amazonaws.com/catalogspreads-pdf/PAGE123%20.100%20SFH11%20SERIES%20FEMALE%20HDR%20ST%20RA.pdf; Lead Time: 11; Mass: N/A; Maximum Operating Temperature: +105DEGC; Minimum Operating Temperature: -40DEGC; Mounting Type: PTH; NOTEfied URL: https://webinterface.notefied-dynamic-precision.com/item/40714083; Number of Positions: 20; Number of Rows: 2; Packing Size: N/A; Packing Type: Missing Info; Part Number: 06-12237; Part Type: Connector|HEADER|STANDARD; Pitch: 2.54mm; REACH/SVHC Compliance: Compliant; REACH/SVHC Details: SVHC List Version Jan 17, 2022 (223); REACH/SVHC Source: REACH Declaration; REACH/SVHC Status: Unaffected; ROHS: Compliant; Rated Current: 3A; Revision: R007; Status: Released; Texas Part Status: Under Review; Type: Connector; Vendor: SULLINS; Vendor Part Status: Active
R70 R71 = RESISTOR: RESISTOR, THICK FILM, 10k, -5%/+5%, 0.063W, 50V, -55DEGC/+155DEGC, 0402, SMD; Additional Datasheet URL: https://www.vishay.com/en/product/20035/; Budgetary Price: .014 EUR; Country of Origin: China, Israel, Taiwan; Datasheet URL: https://www.vishay.com/docs/20035/dcrcwe3.pdf; Lead Time: 18; Mass: 0.00065g; Maximum Operating Temperature: +155DEGC; Maximum Temperature Coefficient: +200PPM/DEGC; Maximum Tolerance: +5%; Minimum Operating Temperature: -55DEGC; Minimum Temperature Coefficient: -200PPM/DEGC; Minimum Temperature Coeficient: -200PPM/DEGC; Minimum Tolerance: -5%; Mounting Type: SMD; NOTEfied URL: https://webinterface.notefied-dynamic-precision.com/item/7252946; Notes: Standard item: Duplicate Reason: custom footprint for TEXAS INSTRUMENTS NORWAY.; PCB Package: 0402; Packing Size: 10000; Packing Type: Tape & Reel; Part Number: 01-22353; Part Type: Resistor|0402|STANDARD; REACH/SVHC Compliance: Compliant; REACH/SVHC Details: SVHC List Version Jan 23, 2024 (240); REACH/SVHC Source: REACH Declaration & Material Declaration; REACH/SVHC Status: Unaffected; ROHS: Exempt; Rated Current: N/A; Rated Power: 0.063W; Rated Voltage: 50V; Resistor Type: THICK FILM; Revision: R037; Status: Released; Texas Part Status: Under Review; Type: Resistor; Vendor: VISHAY; Vendor Part Number: CRCW040210K0JNED; Vendor Part Status: Active
U4 = IC_EEPROM_CAT24C08_TSOT23-5: IC, MEMORY, EEPROM, SERIAL, I2C, 8kbit, 1k X 8bit, 900ns, 1.7V TO 5.5V, TSOT23-5, SMD; ALT_SYMBOLS: SOT95P280X100-5A2L,SOT95P280X100-5A2M; Additional Datasheet URL: https://www.onsemi.com/products/timing-logic-memory/memory/eeprom-memory/cat24c08; Budgetary Price: .1867 USD; Country of Origin: Thailand, United States; Datasheet URL: https://www.onsemi.com/download/data-sheet/pdf/cat24c01-d.pdf; Lead Time: 23; Mass: 0.01268g; Maximum Operating Temperature: +85DEGC; Minimum Operating Temperature: -40DEGC; Mounting Type: SMD; NOTEfied URL: https://webinterface.notefied-dynamic-precision.com/item/25158614; PCB Package: TSOT23-5; Packing Size: 3000; Packing Type: Tape & Reel; Part Number: 18-36044; Part Type: IC|EEPROM|SERIAL|I2C; REACH/SVHC Compliance: Compliant; REACH/SVHC Details: SVHC List Version Jan 16, 2020 (205); REACH/SVHC Source: REACH Declaration; REACH/SVHC Status: Unaffected; ROHS: Compliant; Revision: R019; Status: Released; Texas Part Status: Under Review; Type: IC; Vendor: ONSEMI; Vendor Part Number: CAT24C08TDI-GT3; Vendor Part Status: Active
FIDU1-FIDU6 = FIDMARK: NON COMPONENT, FIDUCIAL MARK, ROUND 1.27MM, SMD; Additional Datasheet URL: N/A; CLASS: IO; Country of Origin: Missing Info; Datasheet URL: N/A; Mass: N/A; Mounting Type: SMD; NOTEfied URL: https://webinterface.notefied-dynamic-precision.com/item/7504224; Packing Size: N/A; Packing Type: Missing Info; Part Number: 19-00300; Part Type: Non Component|FIDUCIAL; ROHS: Not Applicable; Revision: R030; Status: Released; Texas Part Status: Under Review; Type: Non Component; Vendor: NON_COMPONENT; Vendor Part Number: FIDUCIAL_1.27mm; Vendor Part Status: Active
LBL1 = TI_LOGO_V1: NON COMPONENT, LABEL, TEXAS INSTRUMENTS LOGO; Additional Datasheet URL: N/A; AutoDoc File: https://notefied-dynamic-precision.com/DB/Apps/Desktop/Item/Object.aspx?id=87770; BU Name: TEXAS INSTRUMENTS NORWAY; Country of Origin: Missing Info; Datasheet URL: N/A; Mass: N/A; Mounting Type: NOT APPLY; NOTEfied URL: https://webinterface.notefied-dynamic-precision.com/item/7504541; Notes: Custom item; Packing Size: N/A; Packing Type: Missing Info; Part Number: 19-00350; Part Type: Non Component|LABEL; ROHS: Not Applicable; Revision: R033; Status: Released; Texas Part Status: Under Review; Type: Non Component; Vendor: NON_COMPONENT; Vendor Part Status: Active
LBL2 = TRASH_V2: NON COMPONENT, LABEL, TRASH 7mm; Additional Datasheet URL: N/A; Country of Origin: Missing Info; Datasheet URL: N/A; Mass: N/A; Mounting Type: NOT APPLY; NOTEfied URL: https://webinterface.notefied-dynamic-precision.com/item/14983721; Packing Size: N/A; Packing Type: Missing Info; Part Number: 19-01044; Part Type: Non Component|LABEL; ROHS: Not Applicable; Revision: R026; Status: Released; Texas Part Status: Under Review; Type: Non Component; Vendor: NON_COMPONENT; Vendor Part Status: Active
LBL3 = ESD_LABEL: NON COMPONENT, LABEL, ESD, 5 X 5 mm; Additional Datasheet URL: N/A; Country of Origin: Missing Info; Datasheet URL: N/A; Mass: N/A; Maximum Operating Temperature: N/A; Minimum Operating Temperature: N/A; Mounting Type: NOT APPLY; NOTEfied URL: https://webinterface.notefied-dynamic-precision.com/item/7504774; Packing Size: N/A; Packing Type: Missing Info; Part Number: 19-00471; Part Type: Non Component|LABEL; ROHS: Not Applicable; Revision: R010; Status: Released; Type: Non Component; Vendor: NON_COMPONENT; Vendor Part Status: Active
LBL5 = LABEL_FOR_EVALUATOIN_ONLY: NON COMPONENT, LABEL, FOR EVALUATION ONLY, NOT FCC APPROVED FOR RESALE; Additional Datasheet URL: N/A; AutoDoc File: https://notefied-dynamic-precision.com/DB/Apps/Desktop/Item/Object.aspx?id=115268; BU Name: TEXAS INSTRUMENTS NORWAY; Country of Origin: Missing Info; Datasheet URL: N/A; Mass: N/A; Maximum Operating Temperature: N/A; Minimum Operating Temperature: N/A; Mounting Type: NOT APPLY; NOTEfied URL: https://webinterface.notefied-dynamic-precision.com/item/7505603; Notes: Custom item; Packing Size: N/A; Packing Type: Missing Info; Part Number: 19-00830; Part Type: Non Component|LABEL; REACH/SVHC Compliance: Missing Info; REACH/SVHC Details: N/A; REACH/SVHC Source: N/A; REACH/SVHC Status: Missing Info; ROHS: Not Applicable; Revision: R033; Status: Released; Texas Part Status: Under Review; Type: Non Component; Vendor: NON_COMPONENT; Vendor Part Status: Active
LBL6 = CE_LABEL_V1: NON COMPONENT, LABEL, CE; Additional Datasheet URL: N/A; Country of Origin: Missing Info; Datasheet URL: http://www.ce-marking.com/CE-marking-logo.html; Mass: N/A; Mounting Type: NOT APPLY; NOTEfied URL: https://webinterface.notefied-dynamic-precision.com/item/7504539; Packing Size: N/A; Packing Type: Missing Info; Part Number: 19-00351; Part Type: Non Component|LABEL; ROHS: Not Applicable; Revision: R035; Status: Released; Texas Part Status: Under Review; Type: Non Component; Vendor: NON_COMPONENT; Vendor Part Number: CE_LABEL; Vendor Part Status: Active
M1 M2 = MECH_SHUNT_JUMPER_V1: MECHANICAL, SHUNT, CURRENT RATING 4.3A PER PIN, 2.54 X 5.08 X 6.1mm, BLACK; Additional Datasheet URL: https://www.samtec.com/products/snt-100-bk-g; Budgetary Price: .19442 USD; Country of Origin: China, Costa Rica, Malaysia, Singapore, United States, Vietnam; Datasheet URL: https://suddendocs.samtec.com/catalog_english/snt.pdf; Lead Time: 9; Mass: 0.52432g; Maximum Operating Temperature: +125DEGC; Minimum Operating Temperature: -55DEGC; Mounting Type: NOT APPLY; NOTEfied URL: https://webinterface.notefied-dynamic-precision.com/item/7503385; Packing Size: 1; Packing Type: Bulk; Part Number: 19-00498; Part Type: Mechanical|SHUNT; REACH/SVHC Compliance: Compliant; REACH/SVHC Details: SVHC List Version Dec 17, 2015 (168); REACH/SVHC Source: Material Declaration; REACH/SVHC Status: Unaffected; ROHS: Compliant; Status: Released; Texas Part Status: Under Review; Type: Mechanical; Vendor: SAMTEC; Vendor Part Status: Active
M3-M6 = MECH_SPACERS_SUPPORT_V1: MECHANICAL, ACCESSORY, SPACER SUPPORT, PCB DIA. 3mm, NYLON 66, NPTH; Additional Datasheet URL: https://www.kangyang-europe.com/product/dcb-12d/; Country of Origin: Missing Info; Datasheet URL: https://www.kangyang-europe.com/wp-content/uploads/2024/09/DCB-HD-5.pdf; Maximum Operating Temperature: N/A; Minimum Operating Temperature: N/A; Mounting Type: NPTH; NOTEfied URL: https://webinterface.notefied-dynamic-precision.com/item/44342418; Notes: Custom libraries; Packing Size: 1000; Packing Type: Missing Info; Part Number: 13-07898; Part Type: Mechanical|ACCESSORY; REACH/SVHC Compliance: Missing Info; REACH/SVHC Source: N/A; REACH/SVHC Status: Missing Info; ROHS: Compliant; Revision: R005; Status: Released; Texas Part Status: Under Review; Type: Mechanical; Vendor: SUZHOU SOLY ELECTRICIAN; Vendor Part Status: Active
MH1-MH4 = HOLE_PTH: NON COMPONENT, HOLE 3.2mm, PLATED, PAD SIZE 3.8mm; Additional Datasheet URL: N/A; Country of Origin: Missing Info; Datasheet URL: N/A; Mass: N/A; Mounting Type: NOT APPLY; NOTEfied URL: https://webinterface.notefied-dynamic-precision.com/item/7503683; Packing Size: N/A; Packing Type: Missing Info; Part Number: 19-00083; Part Type: Non Component|HOLE|PLATED; ROHS: Not Applicable; Revision: R032; Status: Released; Type: Non Component; Vendor: NON_COMPONENT; Vendor Part Status: Active
MH5 = HOLE_PTH: NON COMPONENT, HOLE 1.1mm, PLATED, PAD SIZE 1.7mm; Additional Datasheet URL: N/A; Country of Origin: Missing Info; Datasheet URL: N/A; Mass: N/A; Mounting Type: NOT APPLY; NOTEfied URL: https://webinterface.notefied-dynamic-precision.com/item/7503643; Packing Size: N/A; Packing Type: Missing Info; Part Number: 19-00062; Part Type: Non Component|HOLE|PLATED; ROHS: Not Applicable; Revision: R009; Status: Released; Type: Non Component; Vendor: NON_COMPONENT; Vendor Part Number: HOLE_1.1mm_PLATED; Vendor Part Status: Active
PCB1 = PCB_V2: NON COMPONENT, PCB, TEXAS INSTRUMENTS; Additional Datasheet URL: https://www.ti.com/; Country of Origin: Missing Info; Datasheet URL: N/A; Mass: N/A; Mounting Type: NOT APPLY; NOTEfied URL: https://webinterface.notefied-dynamic-precision.com/item/14755837; Notes: Custom PCB outline.; Packing Size: N/A; Packing Type: Missing Info; Part Number: 19-00925; Part Type: Non Component|PCB; ROHS: Not Applicable; Status: Released; Texas Part Status: Under Review; Type: Non Component; Vendor: TEXAS INSTRUMENTS; Vendor Part Number: PCB; Vendor Part Status: Active
SC8 = SHIELD_COVER_12: MECHANICAL, SHIELD, SURFACE MOUNT SHIELD FRAME, 19.05 X 19.05 X 5.08, SMD; Additional Datasheet URL: https://leadertechinc.com/circuit-board-shielding/surface-mount-shields/two-piece-surface-mount-shields/; Budgetary Price: 1.21361 USD; CLASS: IC; Country of Origin: United States; Datasheet URL: https://leadertechinc.com/wp-content/uploads/2022/03/SMS_ProductProfile_Web.pdf; Lead Time: 48; Mass: N/A; Maximum Operating Temperature: N/A; Minimum Operating Temperature: N/A; Mounting Type: SMD; NOTEfied URL: https://webinterface.notefied-dynamic-precision.com/item/27985601; Packing Size: 300; Packing Type: Tape & Reel; Part Number: 13-06065; Part Type: Mechanical|SHIELD; REACH/SVHC Compliance: Compliant; REACH/SVHC Details: SVHC List Version Jun 25, 2020 (209); REACH/SVHC Source: REACH Declaration; REACH/SVHC Status: Unaffected; ROHS: Compliant; Revision: R014; Status: Released; Texas Part Status: Under Review; Type: Mechanical; Vendor: LEADER TECH; Vendor Part Status: Active
SC9 = SHIELD_COVER_NOT_APPLY: MECHANICAL, SHIELD, SURFACE MOUNT SHIELD COVER, 18.9 X 18.9 X 2, NOT APPLY; Additional Datasheet URL: https://leadertechinc.com/circuit-board-shielding/surface-mount-shields/two-piece-surface-mount-shields/; Budgetary Price: .30576 USD; Country of Origin: United States; Datasheet URL: https://leadertechinc.com/wp-content/uploads/2022/03/SMS_ProductProfile_Web.pdf; Lead Time: 54; Mass: N/A; Maximum Operating Temperature: N/A; Minimum Operating Temperature: N/A; Mounting Type: NOT APPLY; NOTEfied URL: https://webinterface.notefied-dynamic-precision.com/item/27985699; Packing Size: N/A; Packing Type: Bulk; Part Number: 13-06066; Part Type: Mechanical|SHIELD; REACH/SVHC Compliance: Compliant; REACH/SVHC Details: SVHC List Version Jun 25, 2020 (209); REACH/SVHC Source: REACH Declaration; REACH/SVHC Status: Unaffected; ROHS: Compliant; Revision: R015; Status: Released; Texas Part Status: Under Review; Type: Mechanical; Vendor: LEADER TECH; Vendor Part Status: Active

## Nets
5V0_BP: J1.2 P5.1 P33.18 U4.4(VCC)
GND: C55.2 C112.2 C113.2 CR1.1(C) CR2.1(C) CR8.4(GND) CR9.4(GND) J1.4 J2.2 MH3.1 MH4.1 MH5.1 P1.2 P1.3 P4.3 P4.5 P4.9 P5.2 P5.3 P33.1 P33.7 P33.13 P33.19 P33.20 R71.2 SC8.1(GND) SC8.2(GND) SC8.3(GND) SC8.4(GND) SC8.5(GND) SC8.6(GND) SC8.7(GND) SC8.8(GND) SC8.9(GND) SC8.10(GND) SC8.11(GND) SC8.12(GND) SW1.1 SW1.2 SW1.3 SW2.1 SW2.2 SW2.4 U4.2(VSS) U4.5(WP) U5.4(GND) U5.9(EGP) ; also on sheet 1
DIO0: J2.1 R55.2 ; also on sheet 1
DIO1: J1.7 P33.12 ; also on sheet 1
DIO2: J1.5 P33.14 ; also on sheet 1
DIO3: J1.13 U5.6(SCLK) ; also on sheet 1
DIO4: J2.14 U5.2(SO/SIO1) ; also on sheet 1
DIO5: J2.12 U5.5(SI/SIO0) ; also on sheet 1
DIO7: J2.6 ; also on sheet 1
DIO9_SWDIO: CR8.7(IO6) P4.2 P33.8 R4.2 R70.1 ; also on sheet 1
DIO10_SWDCK: CR8.6(IO5) P4.4 P33.6 R5.2 R71.1 ; also on sheet 1
DIO11: J2.3 R80.2 ; also on sheet 1
DIO11_SWO: CR9.7(IO6) P33.11 R80.1
DIO12: J2.4 P2.4 R21.2 ; also on sheet 1
DIO15: J2.11 R68.1 ; also on sheet 1
DIO16: J2.9 P2.2 R20.2 ; also on sheet 1
DIO17: R72.2 R75.1 ; also on sheet 1
DIO18: R73.2 R74.1 ; also on sheet 1
DIO19: R76.1 R89.2 ; also on sheet 1
DIO19_FLASH_CS: J2.5 R24.1 R89.1 U5.1(nCS)
DIO20: J1.20 R56.2 ; also on sheet 1
DIO21: J1.3 ; also on sheet 1
DIO22: J1.11 ; also on sheet 1
DIO23: J1.9 R19.2 ; also on sheet 1
DIO27: J1.17 R67.1 ; also on sheet 1
DIO28: J1.19 R66.1 ; also on sheet 1
LP_RESET: J2.10 R69.1
RSTN: CR8.3(IO3) P4.10 P33.10 R68.2 R69.2 ; also on sheet 1
WMCU_VDD: C112.1 C113.1 CR8.8(VCC) CR9.8(VCC) J1.1 P1.1 P4.1 P33.16 R22.1 R23.1 R24.2 R25.1 R66.2 R67.2 R70.2 ; also on sheet 1
XDS_BoardID_SCL: P33.15 U4.1(SCL)
XDS_BoardID_SDA: P33.17 U4.3(SDA)
XDS_GPIO1: CR9.3(IO3) P33.3 R19.1
XDS_GPIO2: CR9.5(IO4) P33.5 R20.1
XDS_GPIO3: CR9.6(IO5) P33.9 R21.1
N4030078: J2.13 R4.1
N4030126: J2.15 R5.1
N4030170: J2.17 R72.1
N4030222: J2.19 R73.1
N4030238: J1.14 R74.2
N4030282: J1.16 R75.2
N4030330: J1.18 R76.2
N4030466: P2.1 R14.2
N4030510: P2.3 R15.2
N4030726: R56.1 SW1.4
N4030730: R55.1 SW2.3
N4030734: CR1.2(A) R15.1
N4030738: CR2.2(A) R14.1
N4064546: C55.1 R25.2 U5.8(VCC)
N4065547: R22.2 U5.7(nRESET/SIO3)
N4065551: R23.2 U5.3(nWP/SIO2)

Not connected (* = marked no-connect by the designer): CR8 1(IO1)* 2(IO2)* 5(IO4)*; CR9 1(IO1)* 2(IO2)*; FIDU1 1*; FIDU2 1*; FIDU3 1*; FIDU4 1*; FIDU5 1*; FIDU6 1*; J1 6* 8* 10* 12* 15*; J2 7* 8* 16* 18* 20*; MH1 1*; MH2 1*; P4 6* 7* 8*; P33 2* 4*

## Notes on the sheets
sheet 2
- BoosterPack Headers and Peripherals
- FOR SERIAL BOOTLOADER
  DIO2 -> UART0RX
  DIO1 -> UART0TX
- 40
- 20
- 39
- 19
- 38
- 18
- 37
- 17
- 1
- 2
- 21
- 36
- 16
- 3
- 22
- 23
- 34
- 35
- 14
- 15
- DIO5 -> SPI0POCI/PICO
  DIO4 -> SPI0PICO/POCI
- 4
- 24
- 33
- 13
- 5
- 25
- 32
- 12
- 6
- 26
- 31
- 11
- 7
- 27
- 8
- 9
- 28
- 29
- 10
- 30
- DIO27 -> I2C0SCL
  DIO28 -> I2C0SDA
- DIO18 -> CAN0RX or I2S0WS
  DIO17 -> CAN0TX or I2S0CLK
  DIO19 -> I2S0SDO
  DIO20 -> I2S0SDI
- NOTE:
  R72 and R73 are DNM.
  As default, I2S interface is connected to BoosterPack Header pins BP.31 and BP.32.
  To connect CAN0 interface, remove R72 and R73 and mount R74 and R75.
- 5V and 3V headers
- Buttons
- Place on bottom layer as DNM
- External flash
- DIO5  -> SPI0POCI/PICO
  DIO3  -> SPI0CLK
  DIO19 -> SPI0CSN
  DIO4  -> SPI0PICO/POCI
sheet 3
- XDS110 Debugger Interface
- Board ID
- DIO2 -> UART0RX
  DIO1 -> UART0TX
- DEBUG
- Use P4 for debugging
  the wireless MCU with
  an external debugger
sheet 4
- Mechanical
- Jumpers for P2 LED headers
- Labels
- Mounting Holes
- Fiducials
- PCB
- Standoffs
- Shield
